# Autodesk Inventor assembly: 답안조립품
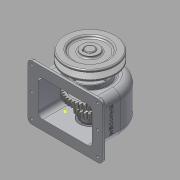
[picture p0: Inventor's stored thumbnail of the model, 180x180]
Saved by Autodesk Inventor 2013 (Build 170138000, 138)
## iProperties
Created: 2015-09
Part Number: 답안조립품
Document SubType Name: Assembly
Designer: dgall
Author: dgall
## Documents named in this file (14)
- C:\Users\dgall\Desktop\09\답안조립품.iam
- C:\Users\dgall\Desktop\09\본체.ipt
- C:\Users\dgall\Desktop\09\축.ipt
- C:\Users\dgall\Desktop\09\V-벨트풀리.ipt
- C:\Users\dgall\Desktop\09\앞커버.ipt
- C:\Users\dgall\Desktop\09\뒤커버.ipt
- C:\Users\dgall\Desktop\09\스퍼기어.ipt
- C:\Users\dgall\Desktop\09\베어링 6203.ipt
- C:\Users\dgall\Desktop\09\볼트 M3 x 8.ipt
- C:\Users\dgall\Desktop\09\볼트 M3 x 10.ipt
- C:\Users\dgall\Desktop\09\오일 실 17 32 8.ipt
- C:\Users\dgall\Desktop\09\키 - 6 x 6 x 22.ipt
- C:\Users\dgall\Desktop\09\키 - 5 x 5 x 18.ipt
- C:\Users\dgall\Desktop\09\멈춤나사 - M4x10.ipt
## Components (9 placed, 3 different names)
1. V-벨트풀리:1
2. ISO 4762 M3 x 8:1
3. ISO 4762 M3 x 8:2
4. ISO 4762 M3 x 8:3
5. ISO 4762 M3 x 8:4
6. ISO 4762 M3 x 10:1
7. ISO 4762 M3 x 10:2
8. ISO 4762 M3 x 10:3
9. ISO 4762 M3 x 10:4
